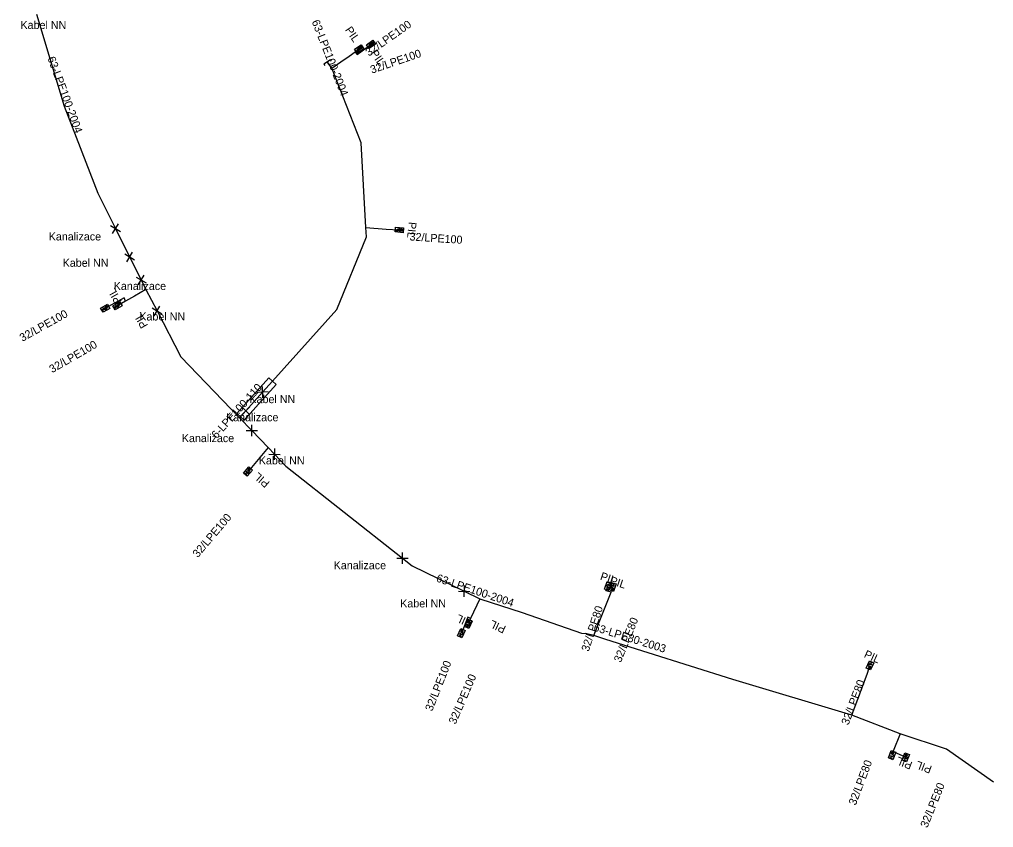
# Model space of a CAD drawing. Extents: x -762509 to -761250, y -1153000 to -1152256.
# Drawn here: x -761371.7 to -761250, y -1152501 to -1152400 of the extents above; entities that cross this region are included whole.
import ezdxf

# ---------------------------------------------------------------- set-up
doc = ezdxf.new("R2010")
doc.units = 0
for name, color, linetype in [('Vrstva 10', 7, 'Continuous'), ('Vrstva 21', 7, 'Continuous'), ('Vrstva 23', 7, 'Continuous'), ('Vrstva 29', 7, 'Continuous'), ('Vrstva 31', 7, 'Continuous'), ('Vrstva 32', 7, 'Continuous')]:
    doc.layers.add(name, color=color, linetype=linetype)

msp = doc.modelspace()

# ---------------------------------------------------------------- linework, layer by layer
at = {"layer": 'Vrstva 10'}
for p, q in [((-761360.327, -1152425.798), (-761359.112, -1152426.522)), ((-761360.082, -1152426.768), (-761359.358, -1152425.553)), ((-761358.557, -1152429.338), (-761357.342, -1152430.062)), ((-761358.312, -1152430.308), (-761357.588, -1152429.093)), ((-761356.872, -1152433.188), (-761356.148, -1152431.973)), ((-761357.117, -1152432.218), (-761355.902, -1152432.942)), ((-761354.882, -1152437.058), (-761354.158, -1152435.843)), ((-761355.127, -1152436.088), (-761353.912, -1152436.812)), ((-761340.623, -1152446.569), (-761342.036, -1152446.63)), ((-761341.299, -1152447.306), (-761341.361, -1152445.893)), ((-761342.938, -1152448.441), (-761343.941, -1152449.439)), ((-761343.938, -1152448.439), (-761342.941, -1152449.441)), ((-761343.387, -1152451.389), (-761341.973, -1152451.412)), ((-761342.692, -1152452.107), (-761342.669, -1152450.693)), ((-761339.842, -1152455.077), (-761339.819, -1152453.663)), ((-761340.537, -1152454.359), (-761339.123, -1152454.382)), ((-761324.567, -1152467.329), (-761323.153, -1152467.352)), ((-761323.872, -1152468.047), (-761323.849, -1152466.633)), ((-761316.142, -1152472.187), (-761316.119, -1152470.773)), ((-761316.837, -1152471.469), (-761315.423, -1152471.492))]:
    msp.add_line(p, q, dxfattribs=at)
at = {"layer": 'Vrstva 21'}
for points in [[(-761369.58, -1152399.37), (-761366.15, -1152410.89), (-761361.93, -1152421.73), (-761359.72, -1152426.16), (-761357.95, -1152429.7), (-761356.51, -1152432.58), (-761355.91, -1152433.78), (-761354.52, -1152436.45), (-761351.54, -1152442.19), (-761344.22, -1152449.81)], [(-761344.22, -1152449.81), (-761344.11, -1152449.69), (-761343.44, -1152448.94), (-761341.33, -1152446.6), (-761340.1, -1152445.23), (-761332.05, -1152436.29), (-761328.36, -1152427.18), (-761328.43, -1152426.05), (-761329.01, -1152415.45), (-761332.68, -1152406.14), (-761333.27, -1152405.35)], [(-761344.22, -1152449.81), (-761342.68, -1152451.4), (-761340.62, -1152453.54), (-761339.83, -1152454.37), (-761338.42, -1152455.84), (-761323.86, -1152467.34), (-761322.63, -1152468.31), (-761316.13, -1152471.48), (-761314.21, -1152472.42), (-761308.89, -1152474.13), (-761301.5, -1152476.72), (-761300.99, -1152476.76)], [(-761250, -1152495.32), (-761255.88, -1152491.22), (-761261.65, -1152489.28), (-761267.72, -1152486.98), (-761282.57, -1152482.5), (-761298.45, -1152477.52), (-761299.96, -1152477.02), (-761300.99, -1152476.76)]]:
    msp.add_lwpolyline(points, dxfattribs=at)
at = {"layer": 'Vrstva 23'}
msp.add_lwpolyline([(-761332.742, -1152405.244), (-761332.851, -1152405.077), (-761333.688, -1152405.624), (-761333.579, -1152405.791)], dxfattribs=at)
at = {"layer": 'Vrstva 29'}
msp.add_lwpolyline([(-761343.66, -1152450.09), (-761339.65, -1152445.63), (-761340.55, -1152444.83), (-761344.56, -1152449.29)], close=True, dxfattribs=at)
at = {"layer": 'Vrstva 31'}
for points in [[(-761332.68, -1152406.14), (-761331.54, -1152405.33), (-761330.53, -1152404.61), (-761329.78, -1152404.08)], [(-761329.8, -1152404.09), (-761329.53, -1152404.43), (-761327.8, -1152403.15)], [(-761329.78, -1152404.08), (-761329.28, -1152403.73)], [(-761328.43, -1152426.05), (-761325.91, -1152426.22), (-761324.25, -1152426.33)], [(-761355.91, -1152433.78), (-761357.36, -1152434.61), (-761358.46, -1152435.25)], [(-761358.47, -1152435.25), (-761358.65, -1152434.81), (-761360.98, -1152436.12)], [(-761358.46, -1152435.25), (-761359.46, -1152435.82)], [(-761340.62, -1152453.54), (-761343.16, -1152456.53)], [(-761297.76, -1152471.59), (-761298.46, -1152471.41), (-761298.15, -1152470.83)], [(-761297.76, -1152471.58), (-761297.6, -1152470.94)], [(-761299.96, -1152477.02), (-761297.76, -1152471.59), (-761297.76, -1152471.58)], [(-761314.21, -1152472.42), (-761315.34, -1152474.88)], [(-761315.35, -1152474.9), (-761315.7, -1152474.73), (-761316.49, -1152476.72)], [(-761315.34, -1152474.88), (-761315.64, -1152475.54)], [(-761267.72, -1152486.98), (-761265.73, -1152481.73), (-761265.44, -1152480.74)], [(-761261.65, -1152489.28), (-761262.53, -1152491.46)], [(-761262.53, -1152491.46), (-761262.54, -1152491.49), (-761262.68, -1152491.96)], [(-761262.54, -1152491.49), (-761260.96, -1152492.22)]]:
    msp.add_lwpolyline(points, dxfattribs=at)
at = {"layer": 'Vrstva 32'}
for p, q in [((-761327.727, -1152402.893), (-761327.527, -1152403.18)), ((-761327.456, -1152402.93), (-761327.621, -1152403.045)), ((-761327.362, -1152403.066), (-761327.562, -1152402.778)), ((-761329.544, -1152403.699), (-761329.346, -1152403.988)), ((-761329.214, -1152403.474), (-761329.017, -1152403.762)), ((-761328.944, -1152403.513), (-761329.11, -1152403.626)), ((-761328.851, -1152403.649), (-761329.048, -1152403.36)), ((-761328.054, -1152403.121), (-761327.854, -1152403.408)), ((-761324.432, -1152426.136), (-761324.467, -1152426.485)), ((-761324.035, -1152426.176), (-761324.07, -1152426.524)), ((-761323.853, -1152426.38), (-761324.053, -1152426.36)), ((-761323.87, -1152426.545), (-761323.835, -1152426.196)), ((-761359.545, -1152436.071), (-761359.72, -1152435.767)), ((-761359.199, -1152435.871), (-761359.374, -1152435.568)), ((-761361.425, -1152436.163), (-761361.253, -1152436.468)), ((-761361.344, -1152436.307), (-761361.169, -1152436.209)), ((-761361.078, -1152436.37), (-761361.249, -1152436.065)), ((-761360.73, -1152436.175), (-761360.901, -1152435.87)), ((-761359.894, -1152435.868), (-761359.719, -1152436.171)), ((-761359.812, -1152436.011), (-761359.637, -1152435.91)), ((-761342.897, -1152456.491), (-761343.164, -1152456.265)), ((-761343.552, -1152456.722), (-761343.286, -1152456.948)), ((-761343.427, -1152456.829), (-761343.296, -1152456.675)), ((-761343.155, -1152456.795), (-761343.422, -1152456.569)), ((-761298.379, -1152470.964), (-761298.047, -1152471.075)), ((-761298.252, -1152470.585), (-761297.92, -1152470.697)), ((-761297.856, -1152470.507), (-761298.188, -1152470.395)), ((-761298.013, -1152470.454), (-761298.077, -1152470.644)), ((-761297.83, -1152471.074), (-761297.497, -1152471.185)), ((-761297.703, -1152470.696), (-761297.371, -1152470.806)), ((-761297.308, -1152470.616), (-761297.64, -1152470.505)), ((-761297.464, -1152470.564), (-761297.528, -1152470.754)), ((-761315.965, -1152475.831), (-761315.647, -1152475.977)), ((-761315.564, -1152475.794), (-761315.882, -1152475.648)), ((-761315.815, -1152475.899), (-761315.732, -1152475.717)), ((-761315.397, -1152475.431), (-761315.715, -1152475.285)), ((-761316.814, -1152477.012), (-761316.496, -1152477.157)), ((-761316.413, -1152476.974), (-761316.731, -1152476.829)), ((-761316.664, -1152477.08), (-761316.581, -1152476.897)), ((-761316.248, -1152476.61), (-761316.566, -1152476.466)), ((-761265.682, -1152480.85), (-761265.363, -1152480.994)), ((-761265.519, -1152480.486), (-761265.199, -1152480.63)), ((-761265.117, -1152480.446), (-761265.436, -1152480.303)), ((-761265.267, -1152480.379), (-761265.35, -1152480.562)), ((-761262.443, -1152491.839), (-761262.769, -1152491.71)), ((-761262.99, -1152492.268), (-761262.665, -1152492.397)), ((-761262.591, -1152492.21), (-761262.916, -1152492.081)), ((-761262.837, -1152492.328), (-761262.763, -1152492.142)), ((-761261.264, -1152492.544), (-761260.936, -1152492.666)), ((-761260.865, -1152492.478), (-761261.193, -1152492.355)), ((-761261.109, -1152492.601), (-761261.039, -1152492.413)), ((-761260.726, -1152492.104), (-761261.054, -1152491.982))]:
    msp.add_line(p, q, dxfattribs=at)
for points in [[(-761327.208, -1152403.111), (-761328.029, -1152403.682), (-761328.372, -1152403.189), (-761327.551, -1152402.619), (-761327.208, -1152403.111)], [(-761327.608, -1152403.237), (-761327.751, -1152403.031), (-761327.791, -1152402.999), (-761327.835, -1152402.989), (-761327.879, -1152402.999), (-761327.903, -1152403.016), (-761327.928, -1152403.054), (-761327.933, -1152403.097), (-761327.916, -1152403.146), (-761327.773, -1152403.352)], [(-761328.698, -1152403.696), (-761329.523, -1152404.26), (-761329.862, -1152403.765), (-761329.036, -1152403.201), (-761328.698, -1152403.696)], [(-761329.346, -1152403.988), (-761329.453, -1152404.061), (-761329.498, -1152404.071), (-761329.519, -1152404.066), (-761329.549, -1152404.047), (-761329.577, -1152404.005), (-761329.584, -1152403.97), (-761329.581, -1152403.949), (-761329.556, -1152403.911), (-761329.449, -1152403.838)], [(-761329.098, -1152403.818), (-761329.24, -1152403.611), (-761329.279, -1152403.579), (-761329.323, -1152403.569), (-761329.368, -1152403.579), (-761329.392, -1152403.595), (-761329.417, -1152403.633), (-761329.422, -1152403.676), (-761329.406, -1152403.725), (-761329.264, -1152403.932)], [(-761327.854, -1152403.408), (-761327.961, -1152403.482), (-761328.005, -1152403.492), (-761328.027, -1152403.488), (-761328.057, -1152403.469), (-761328.086, -1152403.428), (-761328.093, -1152403.393), (-761328.09, -1152403.371), (-761328.065, -1152403.333), (-761327.958, -1152403.259)], [(-761323.783, -1152426.679), (-761324.778, -1152426.579), (-761324.718, -1152425.982), (-761323.723, -1152426.082), (-761323.783, -1152426.679)], [(-761324.467, -1152426.485), (-761324.596, -1152426.472), (-761324.636, -1152426.45), (-761324.649, -1152426.433), (-761324.66, -1152426.399), (-761324.655, -1152426.349), (-761324.638, -1152426.318), (-761324.621, -1152426.303), (-761324.578, -1152426.29), (-761324.448, -1152426.303)], [(-761324.168, -1152426.515), (-761324.143, -1152426.265), (-761324.152, -1152426.215), (-761324.18, -1152426.179), (-761324.22, -1152426.158), (-761324.248, -1152426.155), (-761324.292, -1152426.167), (-761324.324, -1152426.197), (-761324.343, -1152426.245), (-761324.368, -1152426.494)], [(-761361.573, -1152436.103), (-761360.701, -1152435.614), (-761360.407, -1152436.137), (-761361.279, -1152436.626), (-761361.573, -1152436.103)], [(-761360.901, -1152435.87), (-761360.788, -1152435.806), (-761360.743, -1152435.8), (-761360.722, -1152435.807), (-761360.694, -1152435.829), (-761360.669, -1152435.873), (-761360.665, -1152435.908), (-761360.67, -1152435.93), (-761360.699, -1152435.965), (-761360.812, -1152436.028)], [(-761360.043, -1152435.809), (-761359.177, -1152435.31), (-761358.877, -1152435.83), (-761359.744, -1152436.329), (-761360.043, -1152435.809)], [(-761359.634, -1152435.718), (-761359.509, -1152435.935), (-761359.472, -1152435.971), (-761359.429, -1152435.984), (-761359.384, -1152435.978), (-761359.359, -1152435.963), (-761359.331, -1152435.928), (-761359.322, -1152435.885), (-761359.335, -1152435.835), (-761359.46, -1152435.618)], [(-761359.374, -1152435.568), (-761359.262, -1152435.503), (-761359.217, -1152435.497), (-761359.196, -1152435.503), (-761359.167, -1152435.525), (-761359.142, -1152435.568), (-761359.138, -1152435.604), (-761359.143, -1152435.625), (-761359.171, -1152435.661), (-761359.283, -1152435.726)], [(-761361.163, -1152436.016), (-761361.04, -1152436.235), (-761361.004, -1152436.271), (-761360.961, -1152436.285), (-761360.916, -1152436.279), (-761360.89, -1152436.265), (-761360.862, -1152436.23), (-761360.853, -1152436.187), (-761360.865, -1152436.137), (-761360.988, -1152435.918)], [(-761343.712, -1152456.717), (-761343.065, -1152455.955), (-761342.608, -1152456.343), (-761343.255, -1152457.106), (-761343.712, -1152456.717)], [(-761343.358, -1152456.493), (-761343.167, -1152456.656), (-761343.12, -1152456.677), (-761343.075, -1152456.674), (-761343.035, -1152456.653), (-761343.016, -1152456.631), (-761343.002, -1152456.588), (-761343.008, -1152456.545), (-761343.037, -1152456.502), (-761343.228, -1152456.34)], [(-761343.164, -1152456.265), (-761343.08, -1152456.165), (-761343.04, -1152456.144), (-761343.018, -1152456.143), (-761342.983, -1152456.154), (-761342.945, -1152456.186), (-761342.929, -1152456.218), (-761342.927, -1152456.24), (-761342.941, -1152456.283), (-761343.025, -1152456.382)], [(-761297.706, -1152470.452), (-761298.025, -1152471.399), (-761298.593, -1152471.208), (-761298.274, -1152470.26), (-761297.706, -1152470.452)], [(-761297.952, -1152470.791), (-761298.19, -1152470.711), (-761298.241, -1152470.709), (-761298.282, -1152470.727), (-761298.311, -1152470.762), (-761298.321, -1152470.789), (-761298.318, -1152470.834), (-761298.296, -1152470.872), (-761298.254, -1152470.901), (-761298.016, -1152470.981)], [(-761298.047, -1152471.075), (-761298.089, -1152471.198), (-761298.118, -1152471.233), (-761298.138, -1152471.242), (-761298.174, -1152471.245), (-761298.221, -1152471.229), (-761298.248, -1152471.205), (-761298.259, -1152471.186), (-761298.261, -1152471.14), (-761298.22, -1152471.017)], [(-761297.158, -1152470.56), (-761297.474, -1152471.509), (-761298.043, -1152471.319), (-761297.727, -1152470.371), (-761297.158, -1152470.56)], [(-761297.403, -1152470.9), (-761297.641, -1152470.821), (-761297.692, -1152470.819), (-761297.733, -1152470.838), (-761297.762, -1152470.872), (-761297.771, -1152470.9), (-761297.768, -1152470.945), (-761297.746, -1152470.983), (-761297.704, -1152471.012), (-761297.466, -1152471.091)], [(-761297.497, -1152471.185), (-761297.539, -1152471.308), (-761297.568, -1152471.343), (-761297.588, -1152471.352), (-761297.624, -1152471.355), (-761297.671, -1152471.339), (-761297.698, -1152471.315), (-761297.708, -1152471.296), (-761297.711, -1152471.251), (-761297.67, -1152471.127)], [(-761316.121, -1152475.87), (-761315.704, -1152474.961), (-761315.159, -1152475.211), (-761315.575, -1152476.12), (-761316.121, -1152475.87)], [(-761315.84, -1152475.558), (-761315.612, -1152475.663), (-761315.562, -1152475.67), (-761315.519, -1152475.656), (-761315.486, -1152475.625), (-761315.474, -1152475.598), (-761315.472, -1152475.553), (-761315.49, -1152475.513), (-761315.529, -1152475.48), (-761315.757, -1152475.375)], [(-761315.715, -1152475.285), (-761315.661, -1152475.167), (-761315.628, -1152475.136), (-761315.608, -1152475.129), (-761315.572, -1152475.13), (-761315.526, -1152475.151), (-761315.502, -1152475.177), (-761315.494, -1152475.198), (-761315.496, -1152475.243), (-761315.55, -1152475.361)], [(-761316.969, -1152477.052), (-761316.556, -1152476.141), (-761316.01, -1152476.389), (-761316.423, -1152477.3), (-761316.969, -1152477.052)], [(-761316.69, -1152476.739), (-761316.462, -1152476.843), (-761316.411, -1152476.85), (-761316.369, -1152476.836), (-761316.336, -1152476.804), (-761316.324, -1152476.778), (-761316.322, -1152476.733), (-761316.34, -1152476.693), (-761316.379, -1152476.66), (-761316.607, -1152476.556)], [(-761316.566, -1152476.466), (-761316.513, -1152476.347), (-761316.48, -1152476.316), (-761316.459, -1152476.309), (-761316.423, -1152476.31), (-761316.378, -1152476.331), (-761316.354, -1152476.357), (-761316.345, -1152476.377), (-761316.347, -1152476.423), (-761316.401, -1152476.541)], [(-761264.962, -1152480.406), (-761265.372, -1152481.319), (-761265.919, -1152481.073), (-761265.509, -1152480.161), (-761264.962, -1152480.406)], [(-761265.24, -1152480.72), (-761265.469, -1152480.617), (-761265.519, -1152480.61), (-761265.562, -1152480.625), (-761265.595, -1152480.656), (-761265.607, -1152480.682), (-761265.608, -1152480.728), (-761265.59, -1152480.768), (-761265.551, -1152480.801), (-761265.322, -1152480.903)], [(-761265.363, -1152480.994), (-761265.416, -1152481.112), (-761265.449, -1152481.144), (-761265.469, -1152481.151), (-761265.505, -1152481.15), (-761265.551, -1152481.13), (-761265.575, -1152481.103), (-761265.584, -1152481.083), (-761265.582, -1152481.038), (-761265.529, -1152480.919)], [(-761263.143, -1152492.314), (-761262.774, -1152491.385), (-761262.217, -1152491.606), (-761262.585, -1152492.536), (-761263.143, -1152492.314)], [(-761262.879, -1152491.989), (-761262.646, -1152492.081), (-761262.595, -1152492.086), (-761262.553, -1152492.07), (-761262.522, -1152492.037), (-761262.511, -1152492.01), (-761262.512, -1152491.965), (-761262.532, -1152491.925), (-761262.572, -1152491.894), (-761262.805, -1152491.802)], [(-761262.769, -1152491.71), (-761262.721, -1152491.589), (-761262.69, -1152491.556), (-761262.669, -1152491.548), (-761262.633, -1152491.547), (-761262.587, -1152491.566), (-761262.561, -1152491.591), (-761262.552, -1152491.611), (-761262.552, -1152491.656), (-761262.6, -1152491.777)], [(-761261.416, -1152492.594), (-761261.066, -1152491.657), (-761260.504, -1152491.867), (-761260.854, -1152492.804), (-761261.416, -1152492.594)], [(-761261.054, -1152491.982), (-761261.008, -1152491.86), (-761260.977, -1152491.826), (-761260.957, -1152491.818), (-761260.921, -1152491.816), (-761260.875, -1152491.834), (-761260.849, -1152491.859), (-761260.839, -1152491.878), (-761260.838, -1152491.924), (-761260.883, -1152492.045)], [(-761261.159, -1152492.263), (-761260.923, -1152492.35), (-761260.873, -1152492.355), (-761260.831, -1152492.337), (-761260.8, -1152492.304), (-761260.79, -1152492.276), (-761260.791, -1152492.231), (-761260.812, -1152492.192), (-761260.853, -1152492.162), (-761261.088, -1152492.074)]]:
    msp.add_lwpolyline(points, dxfattribs=at)

# ---------------------------------------------------------------- texts
at = {"layer": 'Vrstva 10'}
for s, p in [('Kabel NN', (-761371.59, -1152401.23)), ('Kanalizace', (-761368.06, -1152427.65)), ('Kabel NN', (-761366.32, -1152430.94)), ('Kanalizace', (-761359.94, -1152433.84)), ('Kabel NN', (-761356.74, -1152437.65)), ('Kabel NN', (-761342.98, -1152447.98)), ('Kanalizace', (-761345.9, -1152450.24)), ('Kanalizace', (-761351.43, -1152452.85)), ('Kabel NN', (-761341.81, -1152455.63)), ('Kanalizace', (-761332.45, -1152468.73)), ('Kabel NN', (-761324.14, -1152473.5))]:
    msp.add_text(s, height=1, dxfattribs=at).set_placement(p)
at = {"layer": 'Vrstva 21'}
for s, rotation, p in [('63-LPE100-2004', 291.51435, (-761335.22, -1152400.31)), ('63-LPE100-2004', 290.30424, (-761368.24, -1152404.87)), ('63-LPE100-2004', 341.4586, (-761319.72, -1152470.24)), ('63-LPE80-2003', 342.58847, (-761300.06, -1152476.38))]:
    msp.add_text(s, height=1, rotation=rotation, dxfattribs=at).set_placement(p)
at = {"layer": 'Vrstva 29'}
msp.add_text('6-LPE100-110', height=1, rotation=48.04119, dxfattribs=at).set_placement((-761347.09, -1152452.49))
at = {"layer": 'Vrstva 31'}
for s, rotation, p in [('32/LPE100', 35.14554, (-761328.05, -1152404.69)), ('32/LPE100', 35.14554, (-761328.05, -1152404.69)), ('32/LPE100', 18.87675, (-761327.68, -1152406.82)), ('32/LPE100', 18.87675, (-761327.68, -1152406.82)), ('32/LPE100', 356.20883, (-761323, -1152427.64)), ('32/LPE100', 356.20883, (-761323, -1152427.64)), ('32/LPE100', 29.06083, (-761371.36, -1152440.33)), ('32/LPE100', 29.06083, (-761371.36, -1152440.33)), ('32/LPE100', 29.95014, (-761367.64, -1152444.25)), ('32/LPE100', 29.95014, (-761367.64, -1152444.25)), ('32/LPE100', 49.65216, (-761349.43, -1152467.34)), ('32/LPE100', 49.65216, (-761349.43, -1152467.34)), ('32/LPE80', 72.02773, (-761300.59, -1152479.09)), ('32/LPE80', 72.02773, (-761300.59, -1152479.09)), ('32/LPE80', 67.94435, (-761296.57, -1152480.45)), ('32/LPE80', 67.94435, (-761296.57, -1152480.45)), ('32/LPE100', 68.40728, (-761320.15, -1152486.55)), ('32/LPE100', 68.40728, (-761320.15, -1152486.55)), ('32/LPE100', 66.64826, (-761317.22, -1152488.18)), ('32/LPE100', 66.64826, (-761317.22, -1152488.18)), ('32/LPE80', 69.24091, (-761268.13, -1152488.27)), ('32/LPE80', 69.24091, (-761268.13, -1152488.27)), ('32/LPE80', 69.28809, (-761267.22, -1152498.3)), ('32/LPE80', 69.28809, (-761267.22, -1152498.3)), ('32/LPE80', 67.93684, (-761258.27, -1152501.11)), ('32/LPE80', 67.93684, (-761258.27, -1152501.11))]:
    msp.add_text(s, height=1, rotation=rotation, dxfattribs=at).set_placement(p)
at = {"layer": 'Vrstva 32'}
for rotation, p in [(304.37145, (-761331.08, -1152401.34)), (304.37145, (-761331.08, -1152401.34)), (304.81679, (-761327.92, -1152404.25)), (304.81679, (-761327.92, -1152404.25)), (264.25874, (-761323.08, -1152425.3)), (264.25874, (-761323.08, -1152425.3)), (119.27497, (-761358.87, -1152435.24)), (119.27497, (-761358.87, -1152435.24)), (119.95014, (-761355.62, -1152438.27)), (119.95014, (-761355.62, -1152438.27)), (139.65216, (-761340.36, -1152457.87)), (139.65216, (-761340.36, -1152457.87)), (341.40721, (-761299.23, -1152470.01)), (341.40721, (-761299.23, -1152470.01)), (341.56505, (-761298.03, -1152470.54)), (341.56505, (-761298.03, -1152470.54)), (155.59985, (-761315.03, -1152475.16)), (155.59985, (-761315.03, -1152475.16)), (155.37644, (-761310.84, -1152475.88)), (155.37644, (-761310.84, -1152475.88)), (335.81016, (-761266.27, -1152479.7)), (335.81016, (-761266.27, -1152479.7)), (158.36818, (-761260.05, -1152492.86)), (158.36818, (-761260.05, -1152492.86)), (159.51345, (-761257.61, -1152493.35)), (159.51345, (-761257.61, -1152493.35))]:
    msp.add_text('PIL', height=1, rotation=rotation, dxfattribs=at).set_placement(p)

doc.saveas('drawing.dxf')
